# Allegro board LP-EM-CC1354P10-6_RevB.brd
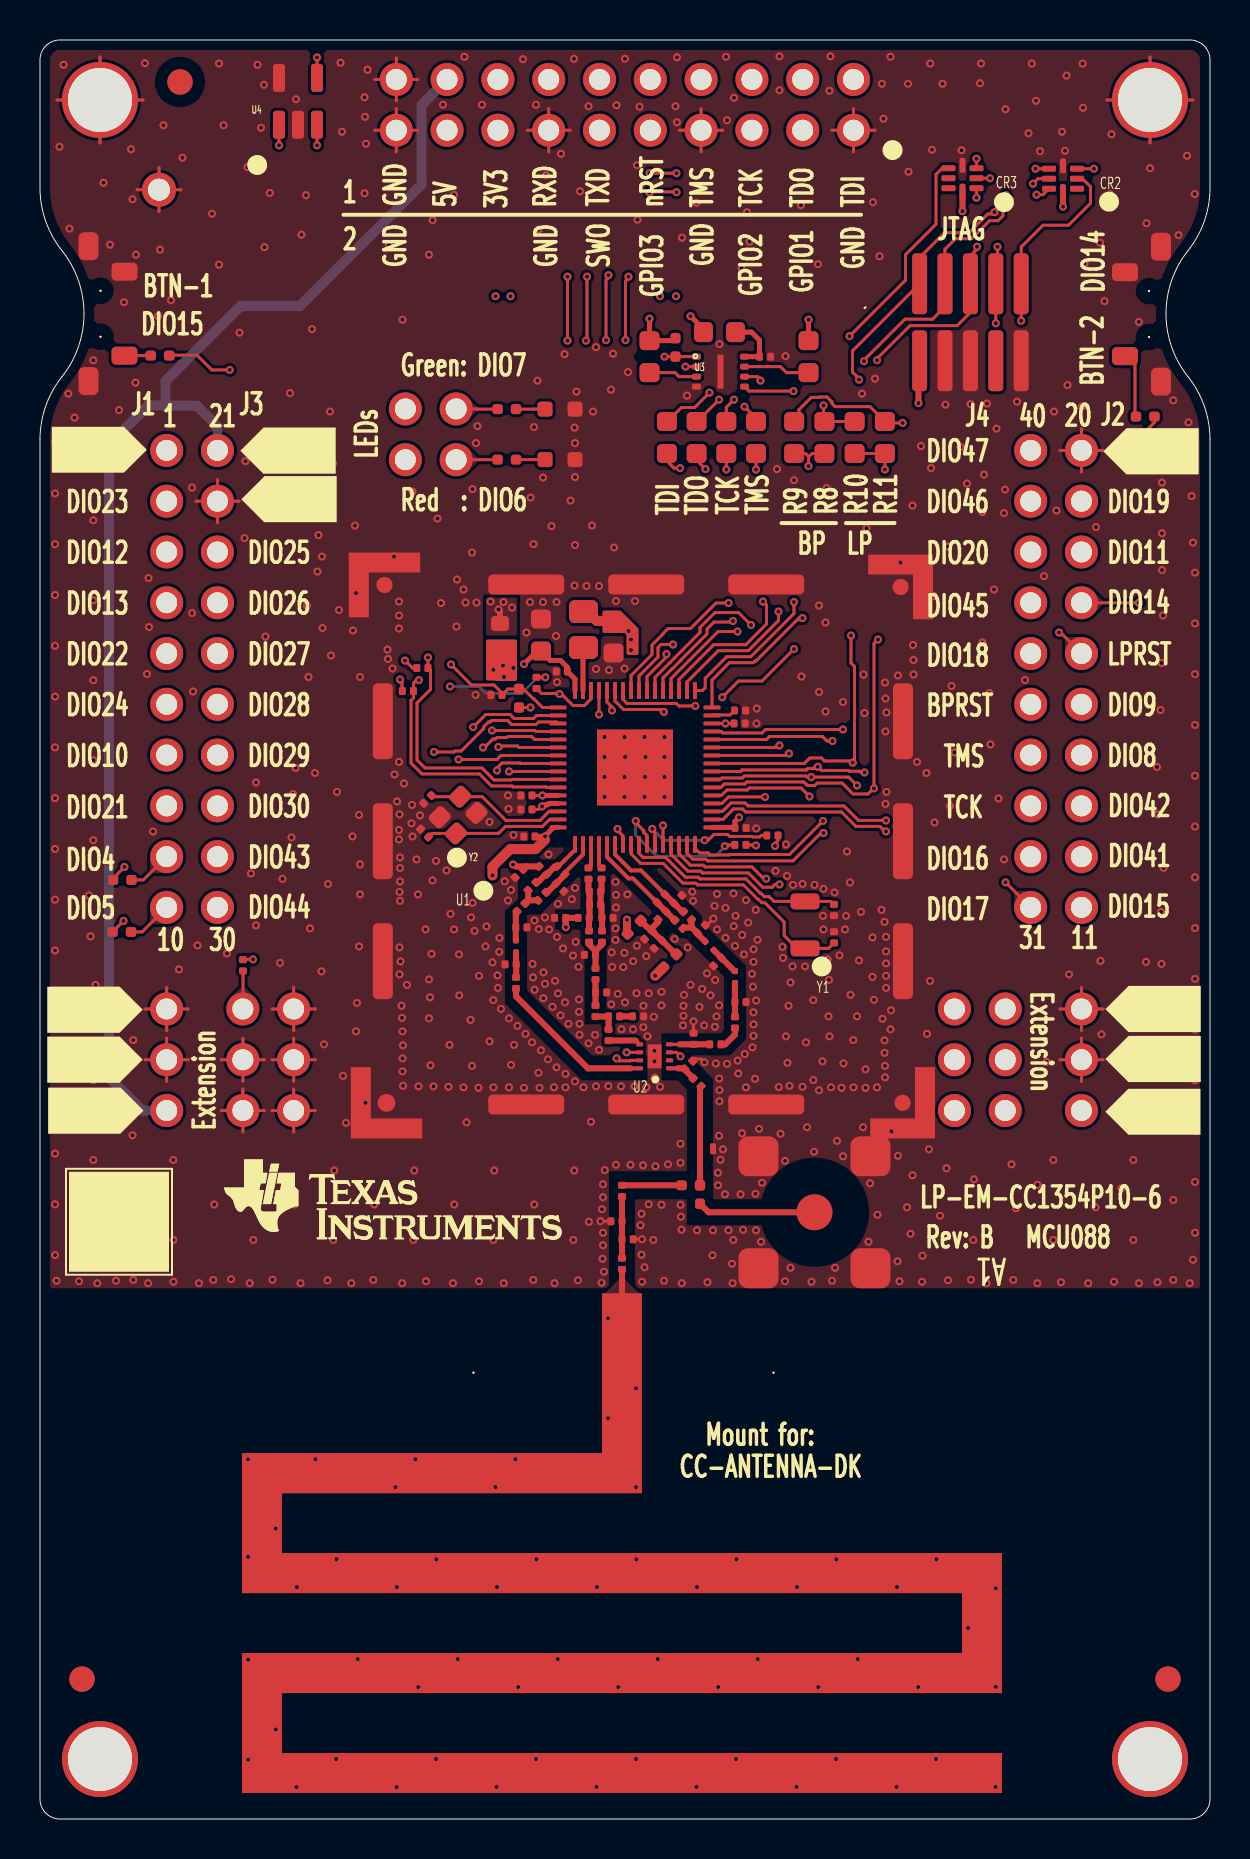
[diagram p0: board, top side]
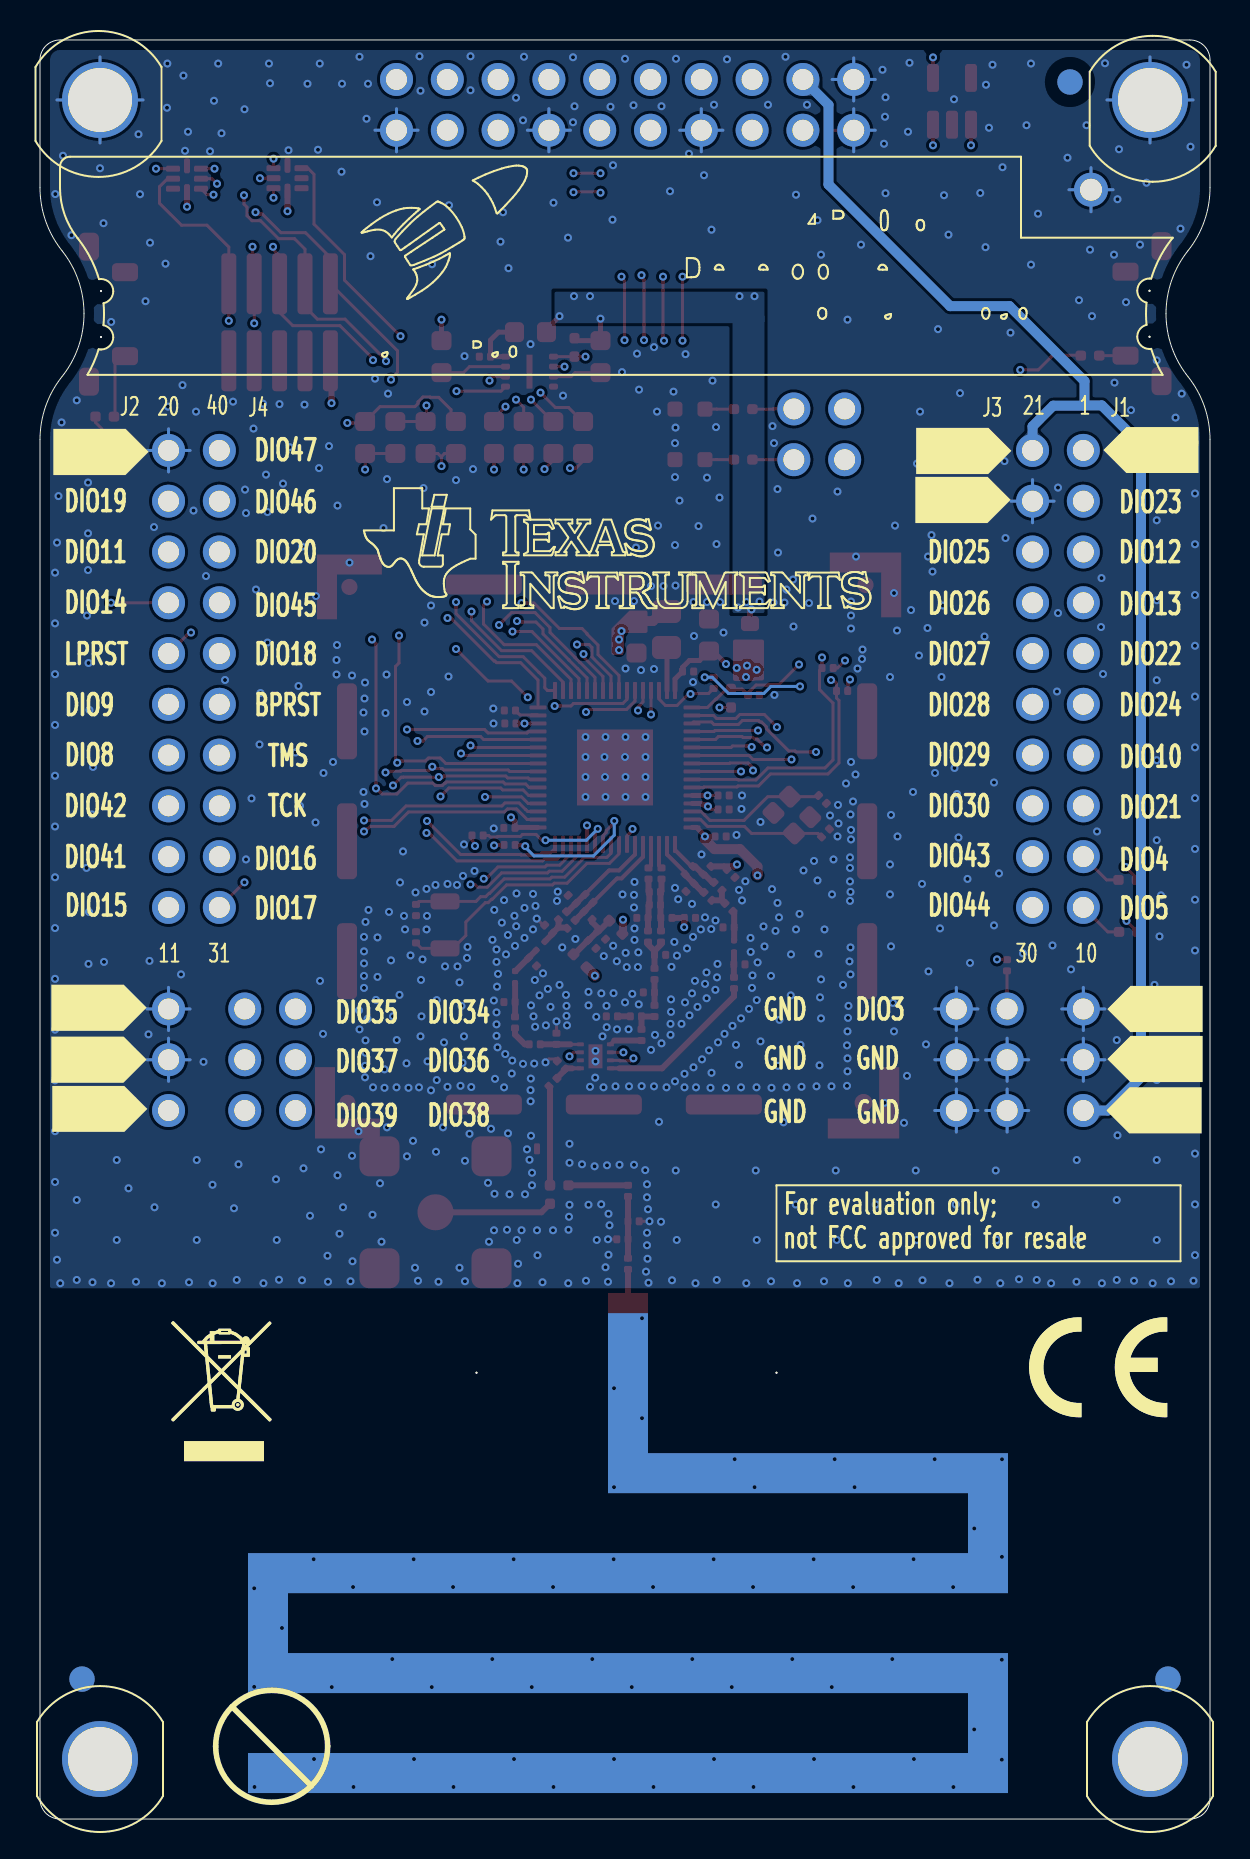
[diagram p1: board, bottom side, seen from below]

Outline 58.5 x 88.99 mm; copper layers: TOP, L2, L3, BOTTOM. Coordinates in mm from the lower left corner of the outline.
Outline path: 0,87.99 0,81.6 arc(0.28,79.93) 1.1,78.45 arc(1.92,76.97) 2.2,75.3 arc(1.92,73.63) 1.1,72.15 arc(0.28,70.67) 0,69 0,1 arc(0.29,0.29) 1,0 57.5,0 arc(58.21,0.29) 58.5,1 58.5,69 arc(58.22,70.67) 57.4,72.15 arc(56.58,73.63) 56.3,75.3 arc(56.58,76.97) 57.4,78.45 arc(58.22,79.93) 58.5,81.6 58.5,87.99 arc(58.21,88.7) 57.5,88.99 1,88.99 arc(0.29,88.7) 0,87.99

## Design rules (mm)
constraint set DEFAULT: min track width 0.15
nets with their own width: min track width 0.15; nets GND VDDR VDDS WMCU_VDD

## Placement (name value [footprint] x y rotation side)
A1  868MHz/2440MHz  [ANTENNA_DN024N]  29.1 25.8 180 top
C1  22uF  [CAPC1608X100A2N]  28.67 59.93 270 top
C2  22uF  [CAPC1608X100A2N]  25.05 58.43 90 top
C3  0.1uF  [CAPC0603X35B2N]  26.38 57.4 180 top
C4  0.1uF  [CAPC0603X35B2N]  34.75 49.57 0 top
C5  0.1uF  [CAPC0603X35B2N]  34.7 54.8 0 top
C6  0.1uF  [CAPC0603X35B2N]  24.6 51.2 180 top
C7  0.1uF  [CAPC0603X35B2N]  24.6 50.5 180 top
C8  0.1uF  [CAPC0603X35B2N]  24.75 49.15 180 top
C9  1uF  [CAPC0603X40B2N]  34.72 55.45 0 top
C11  12pF  [CAPC0603X35B2N]  23.75 47.1 45 top
C12  1pF  [CAPC0603X35B2N]  26.2 46.4 135 top
C13  1pF  [CAPC0603X35B2N]  24.8 46.85 225 top
C14  0.9pF  [CAPC0603X35B2N]  24.35 44.6 180 top
C15  0.6pF  [CAPC0603X35B2N]  23.25 42.75 0 top
C16  12pF  [CAPC0603X35B2N]  23.8 42.1 270 top
C17  47pF  [CAPC1005X60B2N]  33 30.78 90 top
C18  47pF  [CAPC1005X60B2N]  33 31.7 180 top
C27  100pF  [CAPC0603X35B2N]  28.42 39.5 270 top
C31  1.5pF  [CAPC0603X35B2N]  32.09 46.2 225 top
C32  1.5pF  [CAPC0603X35B2N]  31.75 44.95 315 top
C33  12pF  [CAPC0603X35B2N]  30.62 44.41 225 top
C34  10nF  [CAPC0603X35B2N]  31.1 43.94 225 top
C35  1pF  [CAPC0603X35B2N]  32.87 44.32 45 top
C37  1.5pF  [CAPC0603X35B2N]  33.67 42.68 45 top
C38  1.5pF  [CAPC0603X35B2N]  35.3 40.87 180 top
C39  12pF  [CAPC0603X35B2N]  34.75 40.12 270 top
C50  12pF  [CAPC0603X35B2N]  39.7 43.82 90 top
C51  15pF  [CAPC0603X35B2N]  39.7 45.75 270 top
C52  7.5pF  [CAPC0603X35B2N]  19.42 49.12 135 top
C53  7.5pF  [CAPC0603X35B2N]  19.57 51.2 225 top
C54  0.1uF  [CAPC0603X35B2N]  23.1 56.22 180 top
C55  0.1uF  [CAPC0603X35B2N]  35.97 73.15 0 top
C56  100pF  [CAPC0603X35B2N]  25.72 45.07 0 top
C57  3pF  [CAPC0603X35B2N]  27.45 44.43 270 top
C58  2.6pF  [CAPC0603X35B2N]  27.47 46.38 0 top
C59  3pF  [CAPC0603X35B2N]  27.77 43.22 180 top
C60  7pF  [CAPC0603X35B2N]  27.77 41.35 0 top
C61  3pF  [CAPC0603X35B2N]  28.1 45.07 0 top
C62  1.5pF  [CAPC0603X35B2N]  32.68 38.75 90 top
C63  4.7pF  [CAPC0603X35B2N]  32.24 37.52 45 top
CR1  TPD1E0B04DPY  [SON65P100X60X45-2A2N]  33.65 33.53 180 top
CR2  TPD6E004RSE  [QFNFC50P150X150X60-8A2N]  51.85 81.55 90 top
CR3  TPD6E004RSE  [QFNFC50P150X150X60-8A2N]  46.82 81.57 90 top
CR4  LPL296-J2L2-25  [LEDC1707X65N]  26.75 70.53 180 top
CR5  LS L296-P2Q2-1  [LEDC1708X67N]  26.75 68 180 top
FIDU1  FIDU_1.27mm  [FID127X142]  7 86.89 0 top
FIDU2  FIDU_1.27mm  [FID127X142]  2.1 7 0 top
FIDU3  FIDU_1.27mm  [FID127X142]  56.4 7 0 top
FIDU4  FIDU_1.27mm  [FID127X142]  7 86.89 180 bottom
FIDU5  FIDU_1.27mm  [FID127X142]  2.1 7 180 bottom
FIDU6  FIDU_1.27mm  [FID127X142]  56.4 7 180 bottom
FL1  BLM18HE152SN1  [FIL_BLM18HE152SN1DN]  23 58.4 90 top
J1  SSQ-110-23-L-D  [SAMTEC_SSQ11023LD_A2B]  6.33 68.46 0 bottom
J2  SSQ-110-23-L-D  [SAMTEC_SSQ11023LD_A2B]  49.53 68.46 0 bottom
J3  SMA-10V21-TGG  [HUSTSAN_SMA10V21TGGAN]  38.72 30.35 0 top
J4  SFH11-PBPC-D10-RA-BK  [SULLINS_SFH11PBPCD10RABK_A2B]  40.67 84.48 90 top
L1  6.8uH  [INDC2012X150A2N]  27.17 60.4 270 top
L11  20nH  [INDC0603X33A2N]  25.85 47.65 315 top
L12  3.7nH  [INDC0603X33A2N]  24.95 47.65 315 top
L13  3.7nH  [INDC0603X33A2N]  25.3 46.35 225 top
L14  3.4nH  [INDC0603X33A2N]  24.25 45.8 225 top
L15  3.9nH  [IND_LQP03HQ_A2N]  23.8 43.95 270 top
L27  6.8nH  [INDC0603X33A2N]  27.77 40.7 270 top
L34  6.8nH  [INDC0603X33A2N]  30.85 45.85 45 top
L35  2.4nH  [INDC0603X33A2N]  30.9 45 45 top
L36  2.4nH  [INDC0603X33A2N]  32.18 45.38 315 top
L37  3nH  [IND_LQP03HQ_A2N]  33.26 43.89 315 top
L39  3nH  [IND_LQP03HQ_A2N]  34.75 42.41 270 top
L40  10nH  [INDC0603X33A2N]  26.9 45.07 0 top
L41  3.4nH  [INDC0603X33A2N]  27.42 47.57 270 top
L42  22nH  [INDC0603X33A2N]  27.47 45.72 0 top
L43  6.8nH  [INDC0603X33A2N]  27.77 42.55 270 top
L44  3.4nH  [INDC0603X33A2N]  28.07 47.57 270 top
L45  10nH  [INDC0603X33A2N]  28.1 44.43 270 top
LBL1  TI_LOGO  [TI_LOGO_1]  10.2 33 0 top
LBL2  TRASH_7mm  [TRASH_7MM]  51.3 17.9 180 bottom
LBL3  ESD_LABEL_5x5mm  [ESD_LABEL_5X5]  1.45 27.38 0 top
LBL4  CE_label  [CE_MARKING]  6.42 20.1 180 bottom
LBL5  -  [LABEL_FOR_EVALUATION_ONLY]  21.52 28.05 180 bottom
M1  SNT-100-BK-G  [SAMTEC_SNT100BKG]  22.07 69.25 180 top
M2  SNT-100-BK-G  [SAMTEC_SNT100BKG]  22.07 71.8 180 top
M3  DCB-12D  [MECH_DCB12D_A2B]  2.86 85.55 180 bottom
M4  DCB-12D  [MECH_DCB12D_A2B]  55.57 85.79 180 bottom
M5  DCB-12D  [MECH_DCB12D_A2B]  3 3 180 bottom
M6  DCB-12D  [MECH_DCB12D_A2B]  55.5 3 180 bottom
MH1  HOLE_3.2mm_PAD_3.8mm_PTH  [MTG320_380]  3 3 0 top
MH2  HOLE_3.2mm_PAD_3.8mm_PTH  [MTG320_380]  55.5 3 0 top
MH3  HOLE_3.2mm_PAD_3.8mm_PTH  [MTG320_380]  3 85.99 0 top
MH4  HOLE_3.2mm_PAD_3.8mm_PTH  [MTG320_380]  55.5 85.99 0 top
MH5  HOLE_1.1mm_PTH  [MTG110_170]  5.95 81.5 0 top
NOREF  -  []  -1.77 89.3 0 top
NOREF#2  -  []  51.45 66 0 top
NOREF#3  -  []  -4.35 67.3 0 top
NOREF#4  -  []  53.05 34 0 top
NOREF#5  -  []  0.41 88.8 0 top
NOREF#6  -  []  -2.05 32.9 0 top
NOREF#7  -  []  51.55 35.6 0 top
NOREF#8  -  []  51.55 38.1 0 top
NOREF#9  -  []  0 -28.78 0 top
NOREF#10  -  []  8.35 65.9 0 top
NOREF#11  -  []  -1.95 38.1 0 top
NOREF#12  -  []  8.35 63.6 0 top
NOREF#13  -  []  0.23 75.46 0 top
NOREF#14  -  []  53.23 0 90 top
NOREF#15  -  []  0 86.37 0 top
NOREF#16  -  []  -45.65 -52.85 0 top
NOREF#17  #VALUE  [unnamed#2]  21.67 22.32 0 top
NOREF#18  -  []  -1.95 35.6 0 top
NOREF#19  -  []  5.55 67.1 180 bottom
NOREF#20  -  []  17.15 65.9 180 bottom
NOREF#21  -  []  6.85 38.1 180 bottom
NOREF#22  -  []  17.05 63.6 180 bottom
NOREF#23  -  []  51.48 89.52 180 bottom
NOREF#24  -  []  60.25 38.2 180 bottom
NOREF#25  -  []  60.15 66 180 bottom
NOREF#26  -  []  6.85 32.9 180 bottom
NOREF#27  -  []  57.95 34.3 180 bottom
NOREF#28  -  []  6.85 35.6 180 bottom
NOREF#29  -  []  60.25 35.6 180 bottom
P1  BB02-HJ041-KB1-603000  [GRADCONN_BB02HJ041KB1603000_A2B]  20.81 68 90 top
P2  BB02-HC031-KB1-603000  [GRADCONN_BB02HC031KB1603000_A2B]  6.33 35.44 90 top
P3  BB02-HC031-KB1-603000  [GRADCONN_BB02HC031KB1603000_A2B]  52.07 35.44 90 top
P4  BB02-HJ061-KB1-603000  [GRADCONN_BB02HJ061KB1603000_A2B]  10.14 40.52 270 top
P5  BB02-HJ061-KB1-603000  [GRADCONN_BB02HJ061KB1603000_A2B]  45.72 40.52 270 top
P6  FTSH-105-01-F-DV-K  [SAMTEC_FTSH10501FDVK_A2N]  43.98 72.94 0 top
R1  100k  [RESC1005X40B2N]  23.95 56.53 270 top
R2  3.3k  [RESC1005X40B2N]  4.55 44.38 180 top
R3  3.3k  [RESC1005X40B2N]  4.57 46.97 180 top
R4  0  [RESC1608X55A2N]  35.8 68.31 90 top
R5  0  [RESC1608X55A2N]  34.32 68.31 90 top
R6  0  [RESC1608X55A2N]  32.83 68.31 90 top
R7  0  [RESC1608X55A2N]  31.35 68.31 90 top
R8  0  [RESC1608X55A2N]  39.22 68.31 90 top
R9  0  [RESC1608X55A2N]  37.71 68.31 90 top
R10  0  [RESC1608X55A2N]  40.73 68.31 90 top
R11  0  [RESC1608X55A2N]  42.25 68.31 90 top
R12  100  [RESC1005X40B2N]  5.54 73.2 0 top
R13  100  [RESC1005X40B2N]  54.8 70.15 0 top
R14  220  [RESC1005X40B2N]  23.8 70.52 180 top
R15  180  [RESC1005X40B2N]  23.8 68 180 top
R16  0  [RESC0603X35B2N]  10.15 42.43 90 top
R17  0  [RESC0603X35B2N]  35.3 48.72 180 top
R18  0  [RESC0603X35B2N]  36.9 49.2 180 top
R19  0  [RESC0603X35B2N]  24.82 56.55 90 top
R20  0  [RESC0603X35B2N]  19.4 57.57 180 top
R21  0  [RESC0603X35B2N]  18.67 56.43 180 top
R22  0  [RESC1608X55A2N]  38.42 72.35 90 top
R23  0  [RESC1608X55A2N]  30.47 72.35 90 top
R24  2.2k  [RESC1005X40B2N]  31.77 73.15 90 top
R25  0  [RESC1608X55A2N]  34.77 74.38 180 top
R41  0  [RESC1005X40B2N]  30.03 44.94 225 top
R42  0  [RESC1005X40B2N]  31.83 43.25 225 top
SC1  BMIS-203-C  [MECH_BMIS203C]  16.82 35.43 0 top
SF1  BMI-S-203-F  [MECH_BMIS203_A2N]  17.42 35.72 0 top
SW1  1188E-1K2  [SW_1188E1K2V_A2N]  2.42 78.68 270 top
SW2  1188E-1K2  [SW_1188E1K2V_A2N]  56.05 71.9 90 top
U1  CC1354P106T0RSK  [QFNFC40P800X800X100-65A2N]  26.75 48.75 0 top
U2  SKY13317-373  [SON40P150X150X50-9A2N]  31.48 37.55 90 top
U3  MX25R8035FZUIL0  [SON50P300X200X60-9B2L]  32.82 73.15 270 top
U4  CAT24C08TDI  [SOT95P280X100-5A2N]  11.95 84.75 0 top
Y1  32.768kHz  [XTAL_TZ3581F_A2N]  38.25 43.55 90 top
Y2  48MHz  [OSCCC200X160X50-4A2N]  20.8 49.3 45 top
Z1  2.5pF  [CAPC0603X35B2N]  29.1 31.7 270 top
Z2  47pF  [CAPC0603X35B2N]  29.1 28.05 270 top
Z3  5.6pF  [CAPC0603X35B2N]  28.54 29.9 0 top
Z4  27nH  [INDC0603X33A2N]  29.1 29 0 top
Z7  3.9pF  [CAPC0603X35B2N]  28.42 40.15 0 top
Z8  0.6nH  [INDC0603X33A2N]  29.62 40.15 0 top
Z44  0  [RESC0603X35B2N]  33.48 38.75 0 top
Z45  0  [RESC0603X35B2N]  33.05 36.65 135 top

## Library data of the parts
A1 = ANTENNA_PCB: User Part Number: #PN
C1 C2 = CAPACITOR: User Part Number: #PN; alternate symbols: (CAPC1608X100A2L,CAPC1608X100A2M)
C3-C8 C11-C16 C27 C31-C35 C37-C39 C50-C63 Z1-Z3 Z7 = CAPACITOR: User Part Number: #PN; alternate symbols: (CAPC0603X35B2L,CAPC0603X35B2M)
C9 = CAPACITOR: User Part Number: #PN; alternate symbols: (CAPC0603X40B2L,CAPC0603X40B2M)
C17 C18 = CAPACITOR: User Part Number: #PN
CR1 = DIODE_TVS_BIDIR_S: User Part Number: #PN
CR2 CR3 = DIODE_TVS_TPD6E004_QFN8_V1: User Part Number: #PN; alternate symbols: (QFNFC50P150X150X60-8A2L,QFNFC50P150X150X60-8A2M)
CR4 = LED: alternate symbols: (LEDC1707X65L,LEDC1707X65M)
CR5 = LED: alternate symbols: (LEDC1708X67L,LEDC1708X67M)
FIDU1-FIDU6 = FIDMARK
FL1 = FILTER_2PIN: alternate symbols: (FIL_BLM18HE152SN1DL,FIL_BLM18HE152SN1DM)
J1 J2 = CONN_HEADER_2X10_J_S_V1: User Part Number: #PN; alternate symbols: (SAMTEC_SSQ11023LD_A2C,SAMTEC_SSQ11023LD_A2A)
J3 = CONN_COAX_1_4: alternate symbols: (HUSTSAN_SMA10V21TGGL,HUSTSAN_SMA10V21TGGM)
J4 = CONN_HEADER_2X10_P_V3: User Part Number: #PN; alternate symbols: (SULLINS_SFH11PBPCD10RABK_A2A,SULLINS_SFH11PBPCD10RABK_A2C)
L1 = INDUCTOR: User Part Number: #PN; alternate symbols: (INDC2012X150A2L,INDC2012X150A2M)
L11-L14 L27 L34-L36 L40-L45 Z4 Z8 = INDUCTOR: User Part Number: #PN; alternate symbols: (INDC0603X33A2L,INDC0603X33A2M)
L15 L37 L39 = INDUCTOR: User Part Number: #PN; alternate symbols: (IND_LQP03HQ_A2L,IND_LQP03HQ_A2M)
LBL1 = TI_LOGO_V1
LBL2 = TRASH_V2: User Part Number: #PN
LBL3 = ESD_LABEL: User Part Number: #PN
LBL4 = CE_LABEL_V1
LBL5 = LABEL_FOR_EVALUATOIN_ONLY: User Part Number: #PN
M1 M2 = MECH_SHUNT_JUMPER_V1: User Part Number: #PN
M3-M6 = MECH_SPACERS_SUPPORT_V1: User Part Number: #PN
MH1-MH5 = HOLE_PTH
NOREF#17 = -: User Part Number: #PN
P1 = CONN_HEADER_2X2_P: User Part Number: #PN; alternate symbols: (GRADCONN_BB02HJ041KB1603000_A2C,GRADCONN_BB02HJ041KB1603000_A2A)
P2 P3 = CONN_HEADER_3_P_S: User Part Number: #PN; alternate symbols: (GRADCONN_BB02HC031KB1603000_A2C,GRADCONN_BB02HC031KB1603000_A2A)
P4 P5 = CONN_HEADER_2X3_P_V2: User Part Number: #PN; alternate symbols: (GRADCONN_BB02HJ061KB1603000_A2A,GRADCONN_BB02HJ061KB1603000_A2C)
P6 = CONN_HEADER_2X5: User Part Number: #PN; alternate symbols: (SAMTEC_FTSH10501FDVK_A2L,SAMTEC_FTSH10501FDVK_A2M)
R1-R3 R12-R15 R24 R41 R42 = RESISTOR: User Part Number: #PN
R4-R11 R22 R23 R25 = RESISTOR: User Part Number: #PN; alternate symbols: (RESC1608X55A2L,RESC1608X55A2M)
R16-R21 Z44 Z45 = RESISTOR: User Part Number: #PN; alternate symbols: (RESC0603X35B2L,RESC0603X35B2M)
SC1 = SHIELD_COVER: User Part Number: #PN
SF1 = SHIELD_COVER_BMIS-203
SW1 SW2 = SWITCH_TACT_V2: alternate symbols: (SW_1188E1K2V_A2L,SW_1188E1K2V_A2M)
U1 = IC_RF_CC1354P106T0RSK_VQFN64: User Part Number: #PN; alternate symbols: (QFNFC40P800X800X100-65A2L,QFNFC40P800X800X100-65A2M)
U2 = IC_RF_SKY13317-373LF_MLP8: User Part Number: #PN
U3 = IC_FLASH_MX25R8035F_USON8: User Part Number: #PN; alternate symbols: (SON50P300X200X60-9B2L,SON50P300X200X60-9B2M)
U4 = IC_EEPROM_CAT24C08_TSOT23-5: User Part Number: #PN; alternate symbols: (SOT95P280X100-5A2L,SOT95P280X100-5A2M)
Y1 = XTAL: User Part Number: #PN; alternate symbols: (XTAL_TZ3581F_A2L,XTAL_TZ3581F_A2M)
Y2 = XTAL_4PINS_1_3: User Part Number: #PN; alternate symbols: (OSCCC200X160X50-4A2L,OSCCC200X160X50-4A2M)

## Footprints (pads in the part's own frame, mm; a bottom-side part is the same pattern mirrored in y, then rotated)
ANTENNA_DN024N
  rect 2x1 smd: 1(0,0)
CAPC0603X35B2N
  custom 0.087x0.087 smd: 1(0,0) 2(0.56,0)
CAPC0603X40B2N
  custom 0.087x0.087 smd: 1(0,0) 2(0.56,0)
CAPC1005X60B2N
  custom 0.125x0.125 smd: 1(0,0) 2(0.924,0)
CAPC1608X100A2N
  custom 0.237x0.237 smd: 1(0,0) 2(1.6,0)
FID127X142
  round 1.27 smd: 1(0,0)
FIL_BLM18HE152SN1DN
  custom 0.188x0.188 smd: 1(0,0) 2(1.4,0)
GRADCONN_BB02HC031KB1603000_A2B
  round 1.65 hole 1.05: 1(0,0) 2(2.54,0) 3(5.08,0)
GRADCONN_BB02HJ041KB1603000_A2B
  round 1.65 hole 1.05: 1(0,0) 2(0,2.54) 3(2.54,0) 4(2.54,2.54)
GRADCONN_BB02HJ061KB1603000_A2B
  round 1.65 hole 1.05: 1(0,0) 2(0,2.54) 3(2.54,0) 4(2.54,2.54) 5(5.08,0) 6(5.08,2.54)
HUSTSAN_SMA10V21TGGAN
  round 1.8 smd: 1(0,0)
  custom 0.5x0.5 smd: 2(-2.8,-2.8) 3(2.8,-2.8) 4(2.8,2.8) 5(-2.8,2.8)
IND_LQP03HQ_A2N
  custom 0.075x0.075 smd: 1(0,0) 2(0.6,0)
INDC0603X33A2N
  custom 0.087x0.087 smd: 1(0,0) 2(0.56,0)
INDC2012X150A2N
  custom 0.287x0.287 smd: 1(0,0) 2(1.8,0)
LEDC1707X65N
  custom 0.188x0.188 smd: 1(0,0) 2(1.501,0)
LEDC1708X67N
  custom 0.188x0.188 smd: 1(0,0) 2(1.501,0)
MECH_BMIS203_A2N
  custom 0.892x0.892 smd: 1(-0.1,0.1)
  custom 0.25x0.25 smd: 2(6.885,0.015) 3(12.885,0.015) 4(18.885,0.015) 6(25.725,7.185) 7(25.725,13.185) 8(25.725,19.185) 10(18.885,26.025) 11(12.885,26.025) 12(6.885,26.025) 14(-0.285,19.185) 15(-0.285,13.185) 16(-0.285,7.185)
  custom 0.81x0.81 smd: 5(25.705,0.1) 9(25.605,25.905) 13(-0.2,26.005)
MTG110_170
  round 1.699 hole 1.1: 1(0,0)
MTG320_380
  round 3.8 hole 3.2: 1(0,0)
OSCCC200X160X50-4A2N
  custom 0.212x0.212 smd: 1(0,0) 2(1.45,0) 3(1.45,1.15) 4(0,1.15)
QFNFC40P800X800X100-65A2N
  custom 0.05x0.05 smd: 1(0,0) 2(0.4,0) 3(0.8,0) 4(1.2,0) 5(1.6,0) 6(2,0) 7(2.4,0) 8(2.8,0) 9(3.2,0) 10(3.6,0) 11(4,0) 12(4.4,0) 13(4.8,0) 14(5.2,0) 15(5.6,0) 16(6,0) 17(6.85,0.85) 18(6.85,1.25) 19(6.85,1.65) 20(6.85,2.05) 21(6.85,2.45) 22(6.85,2.85) 23(6.85,3.25) 24(6.85,3.65) 25(6.85,4.05) 26(6.85,4.45) 27(6.85,4.85) 28(6.85,5.25) 29(6.85,5.65) 30(6.85,6.05) 31(6.85,6.45) 32(6.85,6.85) 33(6,7.7) 34(5.6,7.7) 35(5.2,7.7) 36(4.8,7.7) 37(4.4,7.7) 38(4,7.7) 39(3.6,7.7) 40(3.2,7.7) 41(2.8,7.7) 42(2.4,7.7) 43(2,7.7) 44(1.6,7.7) 45(1.2,7.7) 46(0.8,7.7) 47(0.4,7.7) 48(0,7.7) 49(-0.85,6.85) 50(-0.85,6.45) 51(-0.85,6.05) 52(-0.85,5.65) 53(-0.85,5.25) 54(-0.85,4.85) 55(-0.85,4.45) 56(-0.85,4.05) 57(-0.85,3.65) 58(-0.85,3.25) 59(-0.85,2.85) 60(-0.85,2.45) 61(-0.85,2.05) 62(-0.85,1.65) 63(-0.85,1.25) 64(-0.85,0.85)
  rect 3.8x3.8 smd: 65(3,3.85)
QFNFC50P150X150X60-8A2N
  custom 0.075x0.075 smd: 1(0,0) 2(0.5,0) 3(1,0) 4(1.145,0.7) 5(1,1.4) 6(0.5,1.4) 7(0,1.4) 8(-0.145,0.7)
RESC0603X35B2N
  custom 0.087x0.087 smd: 1(0,0) 2(0.56,0)
RESC1005X40B2N
  custom 0.125x0.125 smd: 1(0,0) 2(0.924,0)
RESC1608X55A2N
  custom 0.237x0.237 smd: 1(0,0) 2(1.6,0)
SAMTEC_FTSH10501FDVK_A2N
  custom 0.188x0.188 smd: 1(0,0) 2(0,3.85) 3(1.27,0) 4(1.27,3.85) 5(2.54,0) 6(2.54,3.85) 7(3.81,0) 8(3.81,3.85) 9(5.08,0) 10(5.08,3.85)
SAMTEC_SSQ11023LD_A2B
  round 1.65 hole 1.05: 1(0,0) 2(2.54,0) 3(0,2.54) 4(2.54,2.54) 5(0,5.08) 6(2.54,5.08) 7(0,7.62) 8(2.54,7.62) 9(0,10.16) 10(2.54,10.16) 11(0,12.7) 12(2.54,12.7) 13(0,15.24) 14(2.54,15.24) 15(0,17.78) 16(2.54,17.78) 17(0,20.32) 18(2.54,20.32) 19(0,22.86) 20(2.54,22.86)
SON40P150X150X50-9A2N
  custom 0.05x0.05 smd: 1(0,0) 2(0.4,0) 3(0.8,0) 4(1.2,0) 5(1.2,1.5) 6(0.8,1.5) 7(0.4,1.5) 8(0,1.5)
  rect 1.2x0.7 smd: 9(0.6,0.75)
SON50P300X200X60-9B2L
  custom 0.075x0.075 smd: 1(0,0) 2(0.5,0) 3(1,0) 4(1.5,0) 5(1.5,2.4) 6(1,2.4) 7(0.5,2.4) 8(0,2.4)
  rect 1.7x0.3 smd: 9(0.75,1.2)
SON65P100X60X45-2A2N
  custom 0.075x0.075 smd: 1(0,0) 2(0.65,0)
SOT95P280X100-5A2N
  custom 0.15x0.15 smd: 1(0,0) 2(0.95,0) 3(1.9,0) 4(1.9,2.34) 5(0,2.34)
SULLINS_SFH11PBPCD10RABK_A2B
  round 1.65 hole 1.05: 1(0,0) 2(2.54,0) 3(0,2.54) 4(2.54,2.54) 5(0,5.08) 6(2.54,5.08) 7(0,7.62) 8(2.54,7.62) 9(0,10.16) 10(2.54,10.16) 11(0,12.7) 12(2.54,12.7) 13(0,15.24) 14(2.54,15.24) 15(0,17.78) 16(2.54,17.78) 17(0,20.32) 18(2.54,20.32) 19(0,22.86) 20(2.54,22.86)
SW_1188E1K2V_A2N
  round 0.099 hole 0.899 unplated: (2.229,0.6) (4.529,0.6)
  custom 0.25x0.25 smd: 1(0,0) 2(6.75,0)
  custom 0.225x0.225 smd: 3(1.275,1.8) 4(5.475,1.8)
unnamed#2
  round 0.099 hole 3.2 unplated: (0,0) (15,0)
XTAL_TZ3581F_A2N
  custom 0.2x0.2 smd: 1(0,0) 2(2.35,0)

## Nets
5V0_BP: J1.2 J4.18 P2.1 U4.4
GND: C1.2 C2.2 C3.2 C4.2 C5.2 C6.2 C7.2 C8.2 C9.2 C11.1 C12.1 C14.1 C15.1 C31.1 C33.2 C34.2 C35.2 C37.1 C38.1 C50.2 C51.2 C52.2 C53.2 C54.2 C55.2 C56.1 C59.2 C60.2 C61.2 C62.2 C63.2 CR1.1 CR2.4 CR3.4 CR4.1(C) CR5.1(C) J1.4 J2.2 J3.2 J3.3 J3.4 J3.5 J4.1 J4.7 J4.13 J4.19 J4.20 MH3.1 MH4.1 MH5.1 P2.2 P2.3 P3.2 P3.3 P4.2 P4.3 P4.4 P4.5 P4.6 P6.3 P6.5 P6.9 SF1.1 SF1.2 SF1.3 SF1.4 SF1.5 SF1.6 SF1.7 SF1.8 SF1.9(GND#9) SF1.10 SF1.11 SF1.12 SF1.13 SF1.14 SF1.15 SF1.16 SW1.1 SW1.2 SW1.3 SW2.1 SW2.2 SW2.4 U1.65 U2.9 U3.4 U3.9 U4.2 U4.5(WP) Y2.2 Y2.4(GND#4) Z3.1 Z4.2 Z8.2
VDDR: C1.1 C7.1 C8.1 L1.1 R42.2 U1.61 U1.64
VDDS: C2.1 C3.1 C4.1 C5.1 C6.1 FL1.1 R1.2 R41.2 U1.17 U1.30 U1.48 U1.60
BP_RESET: J2.11 R8.1 R9.1
DIO3: P4.1 R16.1 U1.12
DIO3_RF_PA: R16.2 U2.3
DIO4_SCL: J1.17 R3.1 U1.13
DIO5_SDA: J1.19 R2.1 U1.14
DIO6_RLED: P1.2 U1.15
DIO7_GLED: P1.4 U1.16
DIO8_MISO: J2.14 U1.18
DIO9_MOSI: J2.12 U1.19(DIO_9)
DIO10_SCLK: J1.13 U1.20
DIO11: J2.6 U1.21
DIO14_BTN2: J2.8 R13.2 U1.28
DIO15_BTN1: J2.20 R12.2 U1.29
DIO16_TDO: CR2.5 J4.4 P6.6 R6.2 U1.34
DIO17_TDI: CR2.3 J4.2 P6.8 R7.2 U1.35
DIO19: J2.4 U1.37
DIO20: J2.5 U1.38
DIO21: J1.15 U1.39
DIO22: J1.9 U1.40
DIO23_ANALOG: J1.3 U1.50
DIO24_ANALOG: J1.11 U1.51
DIO25_ANALOG: J1.6 U1.52
DIO26_ANALOG: J1.8 U1.53
DIO27_ANALOG: J1.10 U1.54
DIO28_ANALOG: J1.12 U1.55
DIO29_ANALOG: J1.14 U1.56
DIO30_ANALOG: J1.16 U1.57
DIO34: P5.1 R17.2 U1.10
DIO34_RF_2G4: R17.1 U2.7(V3)
DIO35: P5.2 R18.2 U1.11
DIO35_RF_SUB1G: R18.1 U2.6
DIO36_FLASH_MOSI: P5.3 U1.22 U3.5
DIO37_FLASH_MISO: P5.4 U1.23 U3.2
DIO38_FLASH_CS: P5.5 R24.1 U1.24 U3.1
DIO39_FLASH_SCLK: P5.6 U1.25 U3.6
DIO40: R8.2 R10.2 U1.41
DIO41: J2.18 U1.42
DIO42: J2.16 U1.43
DIO43: J1.18 U1.44
DIO44: J1.20 U1.45
DIO45: J2.7 R19.1 U1.46
DIO46: J2.3 R20.1 U1.58
DIO47: J2.1 R21.1 U1.59
LP_RESET: J2.10 R10.1 R11.1
RX_TX: C11.2 C56.2 L12.1 L40.1 U1.7
WMCU_RESET: C54.1 CR2.2 J4.10 P6.10 R1.1 R9.2 R11.2 U1.49
WMCU_RXD: J1.5 J4.14 U1.26
WMCU_SWO: CR3.5 J2.9 J4.11 U1.36
WMCU_TCK: CR2.6 J4.6 P6.4 R5.2 U1.33
WMCU_TMS: CR2.7 J4.8 P6.2 R4.2 U1.32
WMCU_TXD: J1.7 J4.12 U1.27
WMCU_VDD: CR2.8(VCC) CR3.8(VCC) FL1.2 J1.1 J4.16 P3.1 P6.1 R2.2 R3.2 R22.2 R23.2 R24.2 R25.2
XDS_BOARDID_SCL: J4.15 U4.1
XDS_BOARDID_SDA: J4.17 U4.3
XDS_GPIO1: CR3.1 J4.3 R19.2
XDS_GPIO2: CR3.2 J4.5 R20.2
XDS_GPIO3: CR3.3 J4.9 R21.2
N3099875: C13.1 L11.1 L12.2 U1.1
N3099951: C13.2 L13.2 L14.1
N3100073: C14.2 L14.2 L15.1
N3100081: C15.2 C16.1 L15.2
N3100105: C17.1 J3.1
N3100141: C12.2 L11.2 L13.1 U1.2
N3100321: C17.2 C18.1 CR1.2 Z45.1
N3100543: C16.2 U2.8
N3100575: C27.2 U2.5
N3100757: L41.1 U1.3
N3100925: L44.1 U1.4
N3100985: C32.1 L34.1 L35.2 U1.5
N3100993: C18.2 Z1.1
N3100997: C31.2 L34.2 L36.1 U1.6
N3101199: C50.1 U1.8 Y1.1
N3101207: C51.1 U1.9 Y1.2
N3101223: C52.1 U1.63 Y2.1
N3101377: Z1.2 Z2.1 Z3.2 Z4.1
N3101433: A1.1 Z2.2
N3101449: C53.1 U1.62 Y2.3
N3101953: C62.1 U2.4 Z44.1
N3109894: J2.13 R4.1
N3109960: J2.15 R5.1
N3110034: J2.17 R6.1
N3110086: J2.19 R7.1
N3110356: P1.1 R15.2
N3110380: P1.3 R14.2
N3110768: R12.1 SW1.4
N3110772: R13.1 SW2.3
N3110876: CR4.2 R14.1
N3110880: CR5.2 R15.1
N3111246: C55.1 R25.1 U3.8(VCC)
N3111262: R22.1 U3.7
N3111266: R23.1 U3.3
N3254079: L1.2 U1.47
N3281348: C9.1 U1.31
N3492676: C27.1 L27.2 Z7.1
N3492704: Z7.2 Z8.1
N3493209: C57.1 C58.1 L40.2 L41.2 L42.1
N3493257: C57.2 C59.1 L43.1 L45.2
N3493329: C60.1 L27.1 L43.2
N3493341: C58.2 C61.1 L42.2 L44.2 L45.1
N3546372: C33.1 C34.1 L35.1 R41.1 R42.1
N3546508: C32.2 C35.1 L36.2 L37.1
N3546612: C37.2 L37.2 L39.1
N3546624: C38.2 C39.1 L39.2
N3546636: C39.2 Z44.2
N3547384: C63.1 U2.1 Z45.2

Pads without a net: CR2 1; CR3 6 7; FIDU1 1; FIDU2 1; FIDU3 1; FIDU4 1; FIDU5 1; FIDU6 1; MH1 1; MH2 1; P6 7; U2 2

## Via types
v1: diameter 0.4, hole 0.2, TOP to BOTTOM, 1019 vias

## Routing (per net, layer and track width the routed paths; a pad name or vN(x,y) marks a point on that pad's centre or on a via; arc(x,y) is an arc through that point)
5V0_BP: length 75.4
  TOP w0.15: U4.4 v1(13.85,88.12)
  L3 w0.15: J4.18 20.35,87.3 19.26,88.39 14.02,88.39 13.85,88.23 v1(13.85,88.12)
  BOTTOM w0.5: J4.18 20.35,87.01 19.07,85.74 19.07,81.76 12.99,75.68 10.03,75.68 6.27,71.93 6.27,70.71 ; P2.1 5.11,35.44 3.45,37.1 3.45,68.75 5.41,70.71 6.27,70.71 ; J1.2 8.87,69.66 7.84,70.7 6.29,70.7 6.27,70.71
GND: length 307.2
  TOP w0.15: P4.3 10.14,39.06 ; P4.3 11.22,37.98 ; P4.3 10.14,36.9 ; P4.3 9.07,37.98 ; 25.44,83.4 J4.13 ; J4.13 26.51,84.48 ; J4.13 25.44,85.55 ; J4.13 24.36,84.48 ; 40.67,83.4 J4.1 ; J4.1 40.67,85.55 ; J4.1 39.6,84.48 ; J4.1 41.75,84.48 ; P2.3 6.33,41.6 ; P2.3 6.33,39.44 ; P2.3 7.41,40.52 ; P2.3 5.26,40.52 ; 5.26,37.98 P2.2 ; P2.2 6.33,36.9 ; P2.2 7.41,37.98 ; P2.2 6.33,39.06 ; MH4.1 57.65,85.99 ; MH4.1 55.5,83.84 ; MH4.1 55.5,88.14 ; MH4.1 53.35,85.99 ; 16.74,84.48 J4.19 ; J4.19 17.81,85.55 ; J4.19 17.81,83.4 ; J4.19 18.89,84.48 ; 52.07,36.9 P3.2 ; P3.2 52.07,39.06 ; P3.2 51,37.98 ; P3.2 53.15,37.98 ; 12.68,36.9 P4.4 ; P4.4 11.61,37.98 ; P4.4 12.68,39.06 ; P4.4 13.76,37.98 ; 17.81,85.94 J4.20 ; J4.20 17.81,88.09 ; J4.20 18.89,87.01 ; J4.20 16.74,87.01 ; 12.68,39.44 P4.2 ; P4.2 13.76,40.52 ; P4.2 12.68,41.6 ; P4.2 11.61,40.52 ; 32.67,39.31 v1(32.67,39.9) ; 4.85,81.5 MH5.1 ; MH5.1 5.95,80.4 ; MH5.1 5.95,82.6 ; MH5.1 7.05,81.5 ; 33.05,83.4 J4.7 ; J4.7 34.13,84.48 ; J4.7 31.98,84.48 ; J4.7 33.05,85.55 ; v1(33.66,45.04) 33.37,44.75 33.25,44.75 ; P4.5 10.14,36.52 ; P4.5 11.22,35.44 ; P4.5 9.07,35.44 ; P4.5 10.14,34.36 ; P3.3 53.15,40.52 ; P3.3 52.07,39.44 ; P3.3 51,40.52 ; P3.3 52.07,41.6 ; 3,83.84 MH3.1 ; MH3.1 0.85,85.99 ; MH3.1 3,88.14 ; MH3.1 5.15,85.99 ; J2.2 53.15,68.46 ; J2.2 52.07,69.54 ; J2.2 51,68.46 ; J2.2 52.07,67.38 ; Z4.2 v1(30.1,29) ; 11.61,35.44 P4.6 ; P4.6 12.68,36.52 ; P4.6 12.68,34.36 ; P4.6 13.76,35.44 ; C63.2 32.73,38.01 33.06,38.02 v1(33.22,37.85) ; v1(28.03,29.9) Z3.1 ; 7.8,65.92 J1.4 ; J1.4 8.87,67 ; J1.4 9.95,65.92 ; J1.4 8.87,64.84
  L2 w0.15: P2.2 7.41,37.98 ; P2.2 6.33,36.9 ; P2.2 5.26,37.98 ; P2.2 6.33,39.06 ; J4.20 18.89,87.01 ; J4.20 17.81,85.94 ; J4.20 16.74,87.01 ; J4.20 17.81,88.09 ; MH5.1 5.95,82.6 ; MH5.1 5.95,80.4 ; MH5.1 7.05,81.5 ; MH5.1 4.85,81.5 ; P3.2 53.15,37.98 ; P3.2 51,37.98 ; P3.2 52.07,39.06 ; P3.2 52.07,36.9 ; 33.05,83.4 J4.7 ; J4.7 33.05,85.55 ; J4.7 34.13,84.48 ; J4.7 31.98,84.48 ; 9.07,37.98 P4.3 ; P4.3 11.22,37.98 ; P4.3 10.14,36.9 ; P4.3 10.14,39.06 ; 12.68,36.9 P4.4 ; P4.4 11.61,37.98 ; P4.4 12.68,39.06 ; P4.4 13.76,37.98 ; P2.3 6.33,41.6 ; P2.3 7.41,40.52 ; P2.3 6.33,39.44 ; P2.3 5.26,40.52 ; MH4.1 57.65,85.99 ; MH4.1 55.5,83.84 ; MH4.1 55.5,88.14 ; MH4.1 53.35,85.99 ; MH3.1 5.15,85.99 ; MH3.1 3,83.84 ; MH3.1 0.85,85.99 ; MH3.1 3,88.14 ; 12.68,34.36 P4.6 ; P4.6 13.76,35.44 ; P4.6 12.68,36.52 ; P4.6 11.61,35.44 ; P3.3 53.15,40.52 ; P3.3 51,40.52 ; P3.3 52.07,41.6 ; P3.3 52.07,39.44 ; 10.14,34.36 P4.5 ; P4.5 9.07,35.44 ; P4.5 11.22,35.44 ; P4.5 10.14,36.52 ; J1.4 8.87,67 ; J1.4 8.87,64.84 ; J1.4 9.95,65.92 ; J1.4 7.8,65.92 ; J4.13 26.51,84.48 ; J4.13 24.36,84.48 ; J4.13 25.44,83.4 ; J4.13 25.44,85.55 ; 12.68,39.44 P4.2 ; P4.2 11.61,40.52 ; P4.2 12.68,41.6 ; P4.2 13.76,40.52 ; 17.81,83.4 J4.19 ; J4.19 16.74,84.48 ; J4.19 17.81,85.55 ; J4.19 18.89,84.48 ; 40.67,83.4 J4.1 ; J4.1 39.6,84.48 ; J4.1 40.67,85.55 ; J4.1 41.75,84.48 ; J2.2 53.15,68.46 ; J2.2 52.07,69.54 ; J2.2 52.07,67.38 ; J2.2 51,68.46
  L3 w0.15: 16.74,84.48 J4.19 ; J4.19 18.89,84.48 ; J4.19 17.81,85.55 ; MH4.1 57.65,85.99 ; MH4.1 55.5,83.84 ; MH4.1 55.5,88.14 ; MH4.1 53.35,85.99 ; 31.98,84.48 J4.7 ; J4.7 34.13,84.48 ; J4.7 33.05,85.55 ; J4.20 18.89,87.01 ; J4.20 17.81,85.94 ; J4.20 16.74,87.01 ; 3,83.84 MH3.1 ; MH3.1 5.15,85.99 ; MH3.1 3,88.14 ; MH3.1 0.85,85.99 ; 25.44,85.55 J4.13 25.93,85.59 ; 41.79,84.97 J4.1 41.75,84.48 ; 4.85,81.5 MH5.1 5.07,80.62
  BOTTOM w0.15: 5.26,40.52 P2.3 ; P2.3 6.33,41.6 ; P2.3 6.33,39.44 ; P2.3 7.41,40.52 ; 51,37.98 P3.2 ; P3.2 53.15,37.98 ; P3.2 52.07,39.06 ; P3.2 52.07,36.9 ; J4.20 18.89,87.01 ; J4.20 17.81,85.94 ; J4.20 17.81,88.09 ; J4.20 16.74,87.01 ; 0.85,85.99 MH3.1 ; MH3.1 3,88.14 ; MH3.1 3,83.84 ; MH3.1 5.15,85.99 ; 17.81,83.4 J4.19 ; J4.19 17.81,85.55 ; J4.19 16.74,84.48 ; 25.44,83.4 J4.13 ; J4.13 26.51,84.48 ; J4.13 24.36,84.48 ; J4.13 25.44,85.55 ; P4.3 10.14,39.06 ; P4.3 10.14,36.9 ; P4.3 9.07,37.98 ; P4.3 11.22,37.98 ; P2.2 7.41,37.98 ; P2.2 6.33,36.9 ; P2.2 6.33,39.06 ; P2.2 5.26,37.98 ; 52.07,39.44 P3.3 ; P3.3 53.15,40.52 ; P3.3 52.07,41.6 ; P3.3 51,40.52 ; MH4.1 55.5,88.14 ; MH4.1 57.65,85.99 ; MH4.1 55.5,83.84 ; MH4.1 53.35,85.99 ; 12.68,39.44 P4.2 ; P4.2 13.76,40.52 ; P4.2 11.61,40.52 ; P4.2 12.68,41.6 ; P4.4 13.76,37.98 ; P4.4 12.68,36.9 ; P4.4 11.61,37.98 ; P4.4 12.68,39.06 ; P4.6 12.68,36.52 ; P4.6 12.68,34.36 ; P4.6 13.76,35.44 ; P4.6 11.61,35.44 ; 52.07,67.38 J2.2 ; J2.2 52.07,69.54 ; J2.2 53.15,68.46 ; J2.2 51,68.46 ; J1.4 9.95,65.92 ; J1.4 7.8,65.92 ; J1.4 8.87,64.84 ; J1.4 8.87,67 ; 5.95,80.4 MH5.1 ; MH5.1 5.95,82.6 ; MH5.1 4.85,81.5 ; MH5.1 7.05,81.5 ; P4.5 11.22,35.44 ; P4.5 10.14,36.52 ; P4.5 9.07,35.44 ; P4.5 10.14,34.36 ; J4.7 33.05,85.55 ; J4.7 31.98,84.48 ; J4.7 33.05,83.4 ; J4.7 34.13,84.48 ; 40.67,83.4 J4.1 ; J4.1 41.75,84.48 ; J4.1 40.67,85.55 ; J4.1 39.6,84.48
  vias: v1(0.75,68.85) v1(0.75,66.31) v1(0.75,63.77) v1(0.75,61.23) v1(0.75,58.69) v1(0.75,56.15) v1(0.75,53.61) v1(0.75,51.07) v1(0.75,48.53) v1(0.75,45.99) v1(0.75,43.45) v1(0.75,40.91) v1(0.75,38.37) v1(0.75,35.83) v1(0.75,33.29) v1(0.75,30.75) v1(0.75,28.21) v1(0.82,26.93) v1(0.97,83.65) v1(1.17,87.75) v1(1.47,79.55) v1(1.41,71.3) v1(1.72,70.1) v1(1.95,26.9) v1(2.45,46.2) v1(2.52,44.15) v1(2.66,72.97) v1(2.66,68.97) v1(2.66,64.97) v1(2.66,60.97) v1(2.66,56.97) v1(2.66,52.97) v1(2.66,48.97) v1(2.66,36.97) v1(2.66,32.97) v1(2.66,28.97) v1(2.77,41.72) v1(2.87,26.8) v1(3.17,81.85) v1(3.5,78.75) v1(3.8,26.93) v1(3.95,70.47) v1(4.2,75.88) v1(4.55,83.52) v1(4.62,81.02) v1(4.66,38.97) v1(4.62,34.2) v1(4.66,30.97) v1(4.66,26.97) v1(4.8,78.25) v1(4.77,71.85) v1(5.25,87.82) v1(5.35,57.28) v1(5.42,62.07) v1(5.45,59.62) v1(5.41,26.8) v1(5.65,49.4) v1(5.9,75.18) v1(6,78.5) v1(6.17,84.73) v1(6.55,75.97) v1(6.66,32.97) v1(6.66,28.97) v1(6.67,26.88) v1(6.95,42.5) v1(7.12,83.1) v1(7.6,66.6) v1(7.6,60.32) v1(7.65,56.4) v1(7.88,43.7) v1(7.95,26.8) v1(8.6,80.3) v1(8.66,26.97) v1(8.71,30.74) v1(8.95,87.81) v1(8.95,77.75) v1(9.17,84.73) v1(9.35,43.3) v1(9.55,27) v1(9.97,74.35) v1(10.27,67.93) v1(10.22,64.07) v1(10.38,82.62) v1(10.49,26.8) v1(10.55,47.3) v1(10.66,28.97) v1(10.8,51.85) v1(10.8,44.7) v1(10.71,32.44) v1(10.88,87.75) v1(11.05,84.6) v1(11.2,86.75) v1(11.2,65.88) v1(11.22,78.62) v1(11.27,59.15) v1(11.49,81.34) v1(11.62,26.97) v1(12,42.82) v1(12.12,47.03) v1(12.5,71.32) v1(12.57,49.1) v1(12.65,51.28) v1(12.8,86.02) v1(12.77,52.57) v1(12.71,30.74) v1(12.95,69.07) v1(12.95,66.18) v1(13.07,79.25) v1(13.03,26.8) v1(13.3,81.23) v1(13.35,60.7) v1(13.42,57.12) v1(13.5,44.55) v1(13.6,74.53) v1(13.75,52.32) v1(13.88,62.4) v1(13.92,64.22) v1(14.07,42.4) v1(14.1,63.15) v1(14.12,59.57) v1(14.2,38.75) v1(14.38,65.75) v1(14.4,46.78) v1(14.38,26.95) v1(14.5,70.4) v1(14.55,58.2) v1(14.65,67.8) v1(14.66,28.97) v1(14.71,32.44) v1(14.85,51.38) v1(14.95,60.47) v1(15.02,87.85) v1(15.1,84.4) v1(15.15,37.18) v1(15.3,34.82) v1(15.57,26.8) v1(15.65,59.45) v1(15.62,49.15) v1(15.75,64.7) v1(15.8,61.32) v1(15.8,39.4) v1(15.85,40.82) v1(15.95,50.22) v1(15.95,43.65) v1(16,57.12) v1(16,47.75) v1(16,46.25) v1(16.22,86.12) v1(16.25,85.15) v1(16.3,83.8) v1(16.22,81.32) v1(16.27,35.82) v1(16.38,87.5) v1(16.66,26.97) v1(16.71,30.74) v1(17.38,58.5) v1(17.4,58.03) v1(17.45,78.75) v1(17.62,57.55) v1(17.7,63.15) v1(17.72,52.25) v1(17.85,50.9) v1(17.95,60.9) v1(17.95,60.2) v1(17.95,59.55) v1(17.95,52.88) v1(17.97,50.25) v1(17.95,49.47) v1(17.95,49) v1(17.97,46.38) v1(17.97,43.6) v1(17.97,42.25) v1(18,48.1) v1(18,47.57) v1(18,46.9) v1(18,45.93) v1(18.02,42.9) v1(18.07,40.68) v1(18.12,75) v1(18.2,51.8) v1(18.1,40.07) v1(18.12,39.4) v1(18.15,38.7) v1(18.12,38.05) v1(18.12,37.4) v1(18.15,36.68) v1(18.11,26.8) v1(18.35,41.72) v1(18.57,49.8) v1(18.62,66.4) v1(18.6,50.73) v1(18.62,49.15) v1(18.66,28.97) v1(18.71,32.44) v1(18.82,48) v1(18.9,46.25) v1(18.92,36.65) v1(19,50.2) v1(19.27,44.5) v1(19.3,26.9) v1(19.45,78.25) v1(19.45,42) v1(19.45,40.05) v1(19.57,43.28) v1(19.5,41.1) v1(19.52,37.7) v1(19.62,79.97) v1(19.62,46.95) v1(19.67,36.65) v1(19.8,47.93) v1(19.88,65.05) v1(20.05,60.82) v1(20.15,85.75) v1(20.32,47.45) v1(20.47,38.72) v1(20.42,36.62) v1(20.52,45.28) v1(20.65,26.8) v1(20.7,81.25) v1(20.7,44.5) v1(20.71,30.74) v1(20.85,62) v1(20.82,59.65) v1(20.95,43.25) v1(20.96,41.2) v1(21.17,61.5) v1(21.17,36.6) v1(21.22,88.15) v1(21.27,60.85) v1(21.32,34.85) v1(21.55,45.1) v1(21.52,39.97) v1(21.62,66.53) v1(21.6,63.35) v1(21.62,45.82) v1(21.6,37.68) v1(21.8,68.82) v1(21.78,56.23) v1(21.72,44.43) v1(21.88,69.68) v1(21.82,60.85) v1(21.9,46.51) v1(21.95,42.18) v1(21.92,36.57) v1(21.95,26.9) v1(22.1,85.75) v1(22.27,43.65) v1(22.32,44.65) v1(22.47,49.88) v1(22.47,38.9) v1(22.62,42.85) v1(22.66,40.97) v1(22.67,36.6) v1(22.66,28.97) v1(22.71,32.44) v1(22.88,42.2) v1(22.9,41.57) v1(22.97,44.07) v1(22.96,43.37) v1(23.05,40.53) v1(23.19,26.8) v1(23.23,46.91) v1(23.4,51.2) v1(23.4,45.95) v1(23.42,50.53) v1(23.45,40.05) v1(23.45,36.6) v1(23.55,46.47) v1(23.55,37.72) v1(23.67,49.22) v1(23.7,38.72) v1(23.88,39.68) v1(24.15,88.02) v1(24.2,36.57) v1(24.27,39.28) v1(24.32,59.35) v1(24.52,66.1) v1(24.5,60.88) v1(24.67,63.78) v1(24.62,42.78) v1(24.65,42.1) v1(24.6,38.85) v1(24.66,26.97) v1(24.8,85.75) v1(24.7,69.62) v1(24.72,44.95) v1(24.73,41.48) v1(24.71,30.74) v1(24.88,71.95) v1(24.92,79.5) v1(24.94,44.51) v1(24.92,37.32) v1(24.97,36.57) v1(25.05,38.45) v1(25.15,67.1) v1(25.15,60.88) v1(25.17,42.35) v1(25.17,41.06) v1(25.3,82.23) v1(25.25,45.1) v1(25.25,41.78) v1(25.4,38) v1(25.42,48.25) v1(25.46,44.5) v1(25.57,64.68) v1(25.62,40.62) v1(25.8,59.18) v1(25.75,41.93) v1(25.7,36.6) v1(25.73,26.8) v1(25.82,60.88) v1(25.85,56.87) v1(25.9,45.78) v1(25.85,44.12) v1(25.9,41.3) v1(25.82,37.6) v1(26.05,83.3) v1(26.02,40.2) v1(26.15,43.55) v1(26.22,73.28) v1(26.25,40.85) v1(26.27,37.28) v1(26.27,36.6) v1(26.42,39.78) v1(26.52,65.95) v1(26.59,46.01) v1(26.65,43.19) v1(26.66,28.97) v1(26.7,88.05) v1(26.72,69.6) v1(26.75,68.82) v1(26.75,67.12) v1(26.75,63.72) v1(26.72,61.7) v1(26.75,46.57) v1(26.78,43.88) v1(26.75,36.9) v1(26.71,32.44) v1(26.82,71.4) v1(26.9,26.95) v1(26.92,42.62) v1(26.95,41) v1(26.95,40.38) v1(26.97,39.78) v1(26.97,39.22) v1(27,81.43) v1(27.17,36.6) v1(27.32,61.68) v1(27.42,85.68) v1(27.42,38.8) v1(27.45,29.88) v1(27.55,34.88) v1(27.65,70.4) v1(27.6,64.7) v1(27.8,73.62) v1(27.8,57.53) v1(27.75,39.22) v1(27.8,36.65) v1(27.95,61.68) v1(27.95,38.47) v1(28.07,26.82) v1(28.15,31.75) v1(28.15,31.1) v1(28.1,30.5) v1(28.15,29.32) v1(28.15,28.7) v1(28.12,28.03) v1(28.2,27.38) v1(28.22,54.12) v1(28.22,53.12) v1(28.22,52.12) v1(28.22,51.12) v1(28.24,32.46) v1(28.45,57.47) v1(28.42,36.66) v1(28.55,71.5) v1(28.58,43.35) v1(28.56,40.75) v1(28.65,73.3) v1(28.61,42.62) v1(28.7,63.6) v1(28.8,60.93) v1(28.77,46.88) v1(28.8,46.22) v1(28.8,45.6) v1(28.77,44.55) v1(28.77,43.97) v1(28.8,32.72) v1(28.82,85.73) v1(28.89,41.28) v1(29.07,39.5) v1(29.05,36.65) v1(29.16,42.61) v1(29.25,88.05) v1(29.22,57.55) v1(29.22,54.12) v1(29.25,53.12) v1(29.22,52.12) v1(29.22,51.12) v1(29.22,43.33) v1(29.25,40.85) v1(29.4,72.38) v1(29.38,46.25) v1(29.52,32.72) v1(29.66,42.91) v1(29.65,39.5) v1(29.75,60.93) v1(29.72,36.65) v1(29.85,82.73) v1(29.88,80) v1(29.84,43.68) v1(29.82,41.31) v1(29.97,85.65) v1(30.07,30.28) v1(30.02,29.7) v1(30.07,28.22) v1(30.17,40.68) v1(30.17,39.61) v1(30.15,32.7) v1(30.1,26.88) v1(30.22,54.12) v1(30.27,53.12) v1(30.25,52.12) v1(30.22,51.12) v1(30.22,27.6) v1(30.31,43.16) v1(30.38,39.15) v1(30.32,36.6) v1(30.43,41.3) v1(30.44,30.75) v1(30.69,40.12) v1(30.66,28.97) v1(30.72,38.43) v1(30.72,37.9) v1(30.74,37.09) v1(30.77,32.65) v1(31.07,41.38) v1(31.07,40.7) v1(31,36.62) v1(31.07,30.72) v1(31.2,26.93) v1(31.22,54.12) v1(31.22,53.12) v1(31.22,52.12) v1(31.22,51.12) v1(31.4,32.75) v1(31.77,85.68) v1(31.73,44.02) v1(31.85,88.12) v1(31.85,84.88) v1(32.02,33.78) v1(32.02,32.82) v1(32.02,30.72) v1(32.05,30.12) v1(32.07,29.47) v1(32.09,26.8) v1(32.1,79.1) v1(32.2,41.22) v1(32.17,40.68) v1(32.17,40.18) v1(32.15,39.7) v1(32.35,71.2) v1(32.39,43.6) v1(32.52,41.72) v1(32.61,46.39) v1(32.65,45.93) v1(32.82,80.85) v1(32.85,29.45) v1(32.97,40.62) v1(33.11,41.52) v1(33.2,39.7) v1(33.35,42.3) v1(33.38,26.85) v1(33.52,41.2) v1(33.65,29.45) v1(33.62,28.2) v1(33.72,45.68) v1(33.76,41.97) v1(33.74,39.63) v1(33.79,37.79) v1(33.85,46.28) v1(33.85,44.5) v1(33.82,40.15) v1(33.9,32.32) v1(33.9,31.7) v1(33.97,73.78) v1(33.95,40.7) v1(33.96,37.04) v1(33.97,36.46) v1(33.97,35.9) v1(33.95,34.18) v1(34.02,32.97) v1(34.15,33.5) v1(34.3,88.15) v1(34.27,45.57) v1(34.27,44.07) v1(34.25,31.25) v1(34.35,84.98) v1(34.35,37.78) v1(34.42,29.45) v1(34.6,27.78) v1(34.67,46.3) v1(34.69,44.66) v1(34.66,28.97) v1(34.63,26.8) v1(34.7,86.1) v1(34.78,45.18) v1(34.75,43.68) v1(34.89,37.94) v1(34.91,37.29) v1(35.07,77.57) v1(35.02,31.25) v1(35.11,44.22) v1(35.2,43.25) v1(35.1,34.3) v1(35.15,29.47) v1(35.3,45.97) v1(35.24,38.26) v1(35.3,36.6) v1(35.35,80.38) v1(35.47,78.9) v1(35.41,44.84) v1(35.67,43.5) v1(35.67,42.88) v1(35.6,42.28) v1(35.65,41.63) v1(35.67,40.35) v1(35.67,39.75) v1(35.67,39.18) v1(35.62,38.6) v1(35.79,45.48) v1(35.75,37.03) v1(35.77,31.28) v1(35.8,29.45) v1(35.84,55.55) v1(35.82,54.8) v1(35.81,49.55) v1(35.88,43.98) v1(35.81,40.94) v1(35.95,34.53) v1(36.05,28.88) v1(36.1,31.82) v1(36.77,47.43) v1(36.85,67.53) v1(36.97,88.18) v1(36.97,86.48) v1(36.94,36.62) v1(37.02,34.28) v1(37.12,43.62) v1(37.15,43.07) v1(37.27,73.18) v1(37.3,48.75) v1(37.3,39.15) v1(37.25,32.93) v1(37.25,26.9) v1(37.35,47.18) v1(37.38,37.82) v1(37.42,40.68) v1(37.47,36.68) v1(37.52,41.85) v1(37.52,27.57) v1(37.65,46.72) v1(37.62,42.65) v1(37.7,66.97) v1(38.05,80.73) v1(38.07,57.15) v1(38.12,46.78) v1(38.12,36.62) v1(38.25,42.65) v1(38.3,38.85) v1(38.35,34.6) v1(38.57,26.88) v1(38.66,40.97) v1(38.66,36.97) v1(38.72,46.72) v1(38.7,33.38) v1(38.9,77.78) v1(38.95,60.7) v1(38.95,56.38) v1(38.95,36.45) v1(39.17,46.53) v1(39.15,45.18) v1(39.17,44.5) v1(39.12,37.9) v1(39.27,59.85) v1(39.27,55.4) v1(39.32,66.57) v1(39.38,43) v1(39.47,86.45) v1(39.45,41.97) v1(39.42,40.15) v1(39.47,39.15) v1(39.52,88.18) v1(39.55,36.6) v1(39.6,26.93) v1(39.72,46.35) v1(39.75,27.57) v1(39.85,33.93) v1(39.97,43.2) v1(40.07,36.57) v1(40.15,55.88) v1(40.17,37.8) v1(40.15,33.15) v1(40.3,45.18) v1(40.25,44.5) v1(40.35,48.4) v1(40.5,46.85) v1(40.52,41.22) v1(40.66,38.97) v1(40.67,36.6) v1(40.85,40.15) v1(40.95,42.95) v1(41.05,45.38) v1(41.1,71.3) v1(41.15,67.03) v1(41.17,57.25) v1(41.15,34.6) v1(41.22,55.32) v1(41.27,37.5) v1(41.27,36.57) v1(41.32,64.57) v1(41.42,28.88) v1(41.5,31.8) v1(41.65,80.88) v1(41.62,44.1) v1(41.62,42.12) v1(41.75,72.05) v1(41.7,40.97) v1(41.85,36.6) v1(41.88,30.22) v1(41.97,78.18) v1(42.07,45.47) v1(42.1,86.8) v1(42.17,85.05) v1(42.12,40.03) v1(42.25,56.85) v1(42.27,56.05) v1(42.27,54.4) v1(42.27,50.78) v1(42.22,44.88) v1(42.3,44.12) v1(42.3,43.4) v1(42.3,42.8) v1(42.3,42.18) v1(42.3,41.57) v1(42.22,38.95) v1(42.22,38.32) v1(42.25,37.68) v1(42.25,37.1) v1(42.32,55.35) v1(42.32,51.38) v1(42.52,88.15) v1(42.55,40.45) v1(42.52,39.5) v1(42.57,34.4) v1(42.9,57.2) v1(42.9,33.18) v1(42.88,27.9) v1(42.97,26.9) v1(43.02,62.85) v1(43.4,86.8) v1(43.35,30.6) v1(43.42,82.4) v1(43.52,29.28) v1(43.62,65.7) v1(43.65,58.72) v1(43.67,57.97) v1(43.67,57.25) v1(43.62,32.2) v1(43.85,52.88) v1(44.05,68.68) v1(44.12,28.18) v1(44.1,26.88) v1(44.32,52.32) v1(44.35,39.28) v1(44.45,33.5) v1(44.51,87.81) v1(44.55,67.57) v1(44.5,41.93) v1(44.6,83.5) v1(44.7,61.18) v1(44.72,49.85) v1(45,30.18) v1(45.12,86.8) v1(45.27,70.75) v1(45.4,63.65) v1(45.32,32.55) v1(45.4,26.95) v1(45.57,56.68) v1(45.5,50.68) v1(45.72,53.35) v1(46.07,83.48) v1(46.02,68.62) v1(46.35,66.8) v1(46.52,70.78) v1(46.55,26.97) v1(46.66,28.97) v1(46.7,32) v1(47.05,87.81) v1(47,86.82) v1(47.2,67.25) v1(47.12,65.38) v1(47.12,58.85) v1(47.35,70.8) v1(47.33,26.8) v1(47.47,56.32) v1(47.52,53.75) v1(47.7,61.5) v1(47.82,69.55) v1(47.92,51.05) v1(48.2,65.32) v1(48.2,48) v1(48.27,85.52) v1(48.25,66.5) v1(48.57,32.75) v1(48.66,26.97) v1(48.8,30.55) v1(48.85,70.9) v1(49.25,56.97) v1(49.42,84.32) v1(49.59,87.81) v1(49.8,85.95) v1(49.88,31.72) v1(49.87,26.8) v1(50,83.43) v1(50.2,62.18) v1(50.32,37.88) v1(50.66,32.97) v1(50.66,28.97) v1(50.7,70.4) v1(50.82,65.45) v1(51.05,26.85) v1(51.1,84.4) v1(51.25,83.45) v1(51.33,87.21) v1(51.38,71.72) v1(51.45,42.25) v1(52.13,87.81) v1(52.15,85.6) v1(52.1,70.65) v1(52.22,77.8) v1(52.41,26.8) v1(52.8,64.62) v1(52.77,30.6) v1(53,78.85) v1(53.02,42.93) v1(53.07,39.25) v1(53.22,75.93) v1(53.57,84.27) v1(53.5,81.27) v1(53.7,26.88) v1(53.95,35.38) v1(54.07,31.55) v1(54.66,32.97) v1(54.66,28.97) v1(54.94,74.89) v1(54.95,26.8) v1(55.17,35.82) v1(55.3,42.88) v1(55.25,38.7) v1(55.32,79.82) v1(55.5,82.57) v1(55.85,52.62) v1(55.9,50.25) v1(55.88,26.85) v1(55.97,40.07) v1(55.97,37.8) v1(56.1,66.85) v1(56.1,64.31) v1(56.1,62.47) v1(56.07,57.82) v1(56.02,55.47) v1(56.05,45.38) v1(56.07,42.78) v1(56.15,60.2) v1(56.18,47.57) v1(56.66,70.97) v1(56.66,34.97) v1(56.66,30.97) v1(56.66,26.97) v1(56.93,79.22) v1(57.35,83.2) v1(57.32,68.25) v1(57.42,69.86) v1(57.49,26.8) v1(57.57,66.18) v1(57.65,63.85) v1(57.65,27.97) v1(57.74,81.28) v1(57.75,62.35) v1(57.75,59.81) v1(57.75,57.27) v1(57.75,54.73) v1(57.75,52.19) v1(57.75,49.65) v1(57.75,47.11) v1(57.75,44.57) v1(57.75,42.03) v1(57.75,39.49) v1(57.75,36.95) v1(57.75,34.41) v1(57.75,31.87) v1(57.75,29.33)
VDDR: length 38.6
  TOP w0.15: v1(25.1,50.65) 25.07,50.65 24.92,50.5 C7.1 ; 25.25,48.99 v1(25.25,49.15)
  TOP w0.25: 25.22,49.15 25.67,49.6 U1.64 ; 25.22,49.15 C8.1 ; 25.22,49.15 v1(25.25,49.15) ; v1(25.1,50.65) 25.18,50.72 25.32,50.72 25.34,50.75 25.4,50.75 25.45,50.8 U1.61
  TOP w0.5: v1(22.62,47.2) 22.62,47.64 23.5,48.51 24.78,48.51 25.25,48.99 ; 31.17,42.6 v1(30.76,42.18) ; L1.1 27.37,60.4 27.85,59.93 C1.1
  L3 w0.3: v1(25.1,50.65) 24.42,50.65
  L3 w0.5: v1(30.76,42.18) 30.6,42.03 26.67,42.03 24.83,43.86 23.98,43.86 22.62,45.22 v1(22.62,47.2) ; 29.4,58.47 22.8,58.47 22.07,57.74 22.07,56.96 24.42,54.6 24.42,49.98 v1(25.25,49.15)
  vias: v1(29.42,59.43) v1(29.55,59) v1(29.55,58.47)
VDDS: length 40.5
  TOP w0.15: U1.30 v1(34.27,54.8) C5.1 ; v1(24.52,55.6) R1.2 ; C6.1 v1(25.12,51.2)
  TOP w0.25: U1.48 26.75,57.03 C3.1 26.38,57.6 26.03,57.95 25.52,57.95 C2.1 24.85,58.43 v1(24.2,57.78) ; U1.17 34.72,49.6 34.75,49.57 C4.1 34.75,49.9 v1(34.95,50.1) ; U1.60 v1(25.12,51.2)
  TOP w0.3: FL1.1 23,57.9 23.15,57.75
  TOP w0.4: 29.38,44.28 29.35,44.31 v1(29.35,44.98)
  L3 w0.3: 25.12,51.6 v1(25.12,51.2)
  L3 w0.5: v1(34.27,54.8) 34.15,54.68 32.67,54.68 ; 25.12,55.03 25.62,55.03 26.8,56.2 28.82,56.2 30.34,54.69 31.46,54.69 31.47,54.68 32.67,54.68 ; 25.12,55.03 24.55,55.6 v1(24.52,55.6) 23.67,56.45 23.67,56.9 ; 25.12,55.03 25.12,51.6 ; v1(29.35,44.98) 31.72,47.36 31.72,49.35 32.72,50.35 ; 32.72,50.35 32.67,50.4 32.67,54.68 ; 32.72,50.35 32.88,50.5 34.52,50.5 34.92,50.1 v1(34.95,50.1)
  vias: v1(22.67,57.49) v1(23.15,57.7) v1(23.2,57.12) v1(23.66,57.58)
BP_RESET: length 18.9
  TOP w0.15: R9.1 38.27,68.31 38.42,68.16 38.42,68.12 ; 38.42,68.12 38.6,68.31 R8.1 ; 38.42,68.12 v1(38.42,67.68)
  L3 w0.15: J2.11 49.14,55.76 38.42,66.48 v1(38.42,67.68)
DIO3: length 30.8
  TOP w0.15: P4.1 10.15,40.53 R16.1 ; U1.12 v1(31.15,49.7)
  L3 w0.15: v1(31.15,49.7) 30.42,50.43 29.2,50.43 28.72,49.95 28.7,49.95 26.29,47.54 26.27,47.54 26.17,47.45 24.58,47.45 23.5,48.53 22.88,48.53 19.55,45.2 13.17,45.2 11.82,43.85 10.65,43.85 10.14,43.34 P4.1
DIO3_RF_PA: length 32.9
  TOP w0.15: R16.2 10.16,43 v1(10.65,43) ; v1(32.02,38.15) 31.82,38.35 U2.3
  L3 w0.15: v1(10.65,43) 10.65,42.48 11.32,41.8 11.32,34.53 11.52,34.32 29.25,34.32 31.77,36.85 31.77,37.9 v1(32.02,38.15)
DIO4_SCL: length 64
  TOP w0.15: v1(36.97,46.75) 36.75,46.75 36.61,46.61 36.13,46.61 35.42,47.32 33.12,47.32 33.04,47.41 32.39,47.41 31.55,48.26 U1.13 ; J1.17 5.17,46.97 R3.1
  L3 w0.15: J1.17 6.33,47.09 5.28,46.03 5.28,45.16 5.9,44.55 6.03,44.55 8.75,41.83 8.75,34.57 9.6,33.72 29.5,33.72 30.8,35.03 34.77,35.03 36.65,36.9 36.65,38.6 36.67,38.62 36.67,46.45 v1(36.97,46.75)
DIO5_SDA: length 58.8
  TOP w0.15: v1(36.31,47.03) 36.19,47.03 35.6,47.62 33.25,47.62 33.16,47.71 32.52,47.71 31.95,48.28 U1.14 ; J1.19 5.11,44.38 R2.1
  L3 w0.15: J1.19 6.8,45.6 8.96,43.44 8.96,43.14 8.97,43.13 8.97,42.03 9.05,41.95 9.05,34.7 9.72,34.03 29.38,34.03 30.68,35.33 34.65,35.33 36.35,37.03 36.35,44.15 36.31,44.18 v1(36.31,47.03)
DIO6_RLED: length 39.9
  TOP w0.15: v1(39.17,49.32) 39.05,49.32 37.65,47.93 33.38,47.93 33.29,48.01 32.64,48.01 32.35,48.31 U1.15
  L3 w0.15: P1.2 18.27,67.81 23.38,62.7 29.57,62.7 32.2,60.07 32.2,60.07 32.97,59.3 32.97,59.3 35.3,56.97 36.23,56.97 37.92,55.28 37.92,53.17 37.57,52.82 37.57,50.73 38.98,49.32 v1(39.17,49.32)
DIO7_GLED: length 41.3
  TOP w0.15: U1.16 32.75,48.56 32.98,48.32 33.4,48.32 33.5,48.22 34.44,48.22 34.46,48.25 37.47,48.25 v1(39.15,49.93)
  L3 w0.15: v1(39.15,49.93) 38.8,49.93 37.88,50.85 37.88,52.7 38.22,53.05 38.22,55.41 36.36,57.28 35.42,57.28 33.27,59.42 33.27,59.43 32.33,60.38 32.32,60.38 29.65,63.05 23.55,63.05 19.76,66.84 19.76,68.97 18.27,70.46 P1.4
DIO8_MISO: length 32.9
  TOP w0.15: v1(42.3,49.4) 42.25,49.4 42.13,49.53 42.12,49.53 42,49.65 40.8,49.65 40.07,50.38 35.28,50.38 35.13,50.53 34.67,50.53 34.15,50 U1.18
  L3 w0.15: J2.14 53.9,51.39 53.9,45 52.5,43.6 48.1,43.6 v1(42.3,49.4)
DIO9_MOSI: length 37.4
  TOP w0.15: v1(42.3,49.95) 40.92,49.95 40.2,50.68 35.4,50.68 35.25,50.83 34.55,50.83 34.22,50.5 34.22,50.5 34.12,50.4 U1.19
  L3 w0.15: v1(42.3,49.95) 42.27,49.93 42.1,49.93 41.88,49.7 41.88,49.22 47.8,43.3 52.62,43.3 54.2,44.88 54.2,51.52 53.35,52.37 53.35,54.45 52.07,55.73 J2.12
DIO10_SCLK: length 87.2
  TOP w0.15: U1.20 34.1,50.8 34.42,51.13 36.25,51.13 v1(36.25,51.12)
  L3 w0.15: v1(36.25,51.12) 36.25,50.35 38.6,48 40.97,48 47.35,41.62 48.75,41.62 49.47,40.9 49.47,39.82 48.98,39.33 45.3,39.33 44.3,38.32 44.3,37.4 42.96,36.06 36.24,36.06 34.9,34.72 30.93,34.72 29.63,33.43 9.47,33.43 8.45,34.45 8.45,41.62 5.82,44.25 5.77,44.25 4.98,45.04 4.98,51.87 J1.13
DIO11: length 43
  TOP w0.15: U1.21 34.07,51.2 34.34,51.47 35.37,51.47 35.47,51.57 38.05,51.57 v1(38.47,51.15)
  L3 w0.15: J2.6 50.97,62.28 50.97,59.93 51.38,59.53 51.38,59.09 50.65,58.36 50.65,47.3 50.38,47.03 49.05,47.03 48.45,46.43 47.52,46.43 44.22,49.72 44.22,51.78 40.7,55.3 39.88,55.3 39.2,54.62 39.2,52.92 39.31,52.81 39.31,52.46 39.12,52.27 39.12,51.8 v1(38.47,51.15)
DIO14_BTN2: length 51.9
  TOP w0.15: v1(54.95,60.84) J2.8 ; R13.2 55.72,69.86 v1(54.95,69.09) ; U1.28 36.32,54 36.47,54.15 39.12,54.15 39.35,53.93 v1(39.62,53.93)
  L3 w0.15: v1(54.95,60.84) v1(54.95,69.09) ; J2.8 53.2,59.71 53.2,57.8 52.4,57 51.32,57 51.02,56.7 51.02,47.71 51.02,47.7 51.02,47.18 50.5,46.65 49.1,46.65 48.57,46.12 47.4,46.12 43.92,49.6 43.92,51.65 40.62,54.95 39.97,54.95 39.62,54.6 v1(39.62,53.93)
DIO15_BTN1: length 86.7
  TOP w0.15: v1(40.15,54.5) 36.28,54.5 36.1,54.32 34.15,54.32 34.1,54.38 34.07,54.38 34.05,54.4 U1.29 ; R12.2 6.48,73.22 7.85,73.22 8.59,72.49 v1(9.49,72.49)
  L3 w0.15: J2.20 50.97,44.5 48.6,44.5 43.62,49.47 43.62,51.53 41.2,53.95 41.15,53.95 40.6,54.5 v1(40.15,54.5) 40.15,53.85 39.61,53.31 39.61,52.33 39.49,52.21 39.49,51.11 39.6,51 39.6,49.15 39.35,48.9 38.98,48.9 37.27,50.6 37.27,52.67 36.55,53.4 36.55,55.38 35.86,56.07 34.92,56.07 32.07,58.92 32.07,58.93 31.83,59.18 31.82,59.18 30.51,60.49 25.29,60.49 24.88,60.08 22.88,60.08 20.97,58.17 20.97,57.43 20.62,57.08 20.32,57.08 19.78,56.54 13.06,56.54 12.42,57.18 12.42,69.55 v1(9.49,72.49)
DIO16_TDO: length 67.5
  TOP w0.15: v1(33.95,71) 32.86,69.91 R6.2 ; CR2.5 v1(49.77,82.55) ; v1(36.92,60.4) 36.92,59.95 35.42,58.44 33.92,58.44 32.35,56.88 U1.34 ; v1(46.85,78.65) 46.85,78.53 46.52,78.19 P6.6 46.52,75.36 45.86,74.7 43.5,74.7 41.85,73.05 v1(41.85,72.97)
  L3 w0.15: v1(36.92,60.4) 36.92,60.73 36.1,61.55 33.3,61.55 28.8,66.05 28.8,69.03 30.57,70.8 33.75,70.8 v1(33.95,71) 33.95,71.1 34.4,71.55 34.4,71.78 35.6,72.97 36.45,72.97 36.95,72.47 39.62,72.47 40.38,73.22 40.88,73.22 41.05,73.4 41.42,73.4 v1(41.85,72.97) ; J4.4 39.27,85.88 46.6,85.88 48.6,83.88 48.6,83.5 49.55,82.55 v1(49.77,82.55) 49.92,82.55 50.32,82.15 50.32,81.13 48.5,79.3 47.25,79.3 46.85,78.9 v1(46.85,78.65)
DIO17_TDI: length 78.5
  TOP w0.15: U1.35 31.95,57.01 33.69,58.74 35.29,58.74 36.32,59.78 36.32,60.72 v1(36.15,60.9) ; R7.2 31.37,69.91 32.07,70.61 32.73,70.61 v1(33.47,71.35) ; v1(52.7,82.55) CR2.3 ; v1(47.88,78.65) 47.88,78.03 47.79,77.94 P6.8 v1(47.79,74.82)
  L3 w0.15: v1(47.88,78.65) 48.35,78.65 50.82,81.12 51.95,81.12 52.1,81.27 52.1,81.95 v1(52.7,82.55) 52.65,82.6 50.33,82.6 49.95,82.98 49.92,82.98 49.86,83.04 49.84,83.04 49.61,83.26 49.61,83.29 46.67,86.23 41.48,86.23 40.69,87.01 J4.2 ; v1(36.15,60.9) 34.95,60.9 34.6,61.25 33.18,61.25 28.5,65.93 28.5,69.15 30.94,71.59 32.51,71.59 32.74,71.35 v1(33.47,71.35) 33.55,71.35 35.47,73.28 36.58,73.28 37.08,72.78 39.5,72.78 40.25,73.53 40.75,73.53 40.97,73.75 41.68,73.75 42.27,73.15 42.27,70.07 42.97,69.38 46.52,69.38 47.79,70.64 v1(47.79,74.82)
DIO19: length 54.7
  TOP w0.15: v1(34.65,59.93) 34.6,59.88 33.7,59.88 33.35,59.53 33.35,59.28 32.05,57.98 32.05,57.97 31.63,57.55 31.62,57.55 31.15,57.08 U1.37
  L3 w0.15: v1(34.65,59.93) 34.9,60.18 36.02,60.18 36.4,59.8 36.44,59.8 36.94,59.3 38.05,59.3 38.77,58.58 39.12,58.58 39.12,58.57 42.08,58.57 42.32,58.82 42.32,59.18 42.08,59.43 42.08,59.43 38.15,63.35 34.05,63.35 30.6,66.8 30.6,68.28 31.32,69 42.58,69 46.83,64.75 50.9,64.75 J2.4
DIO20: length 52.8
  TOP w0.15: U1.38 30.75,57.1 31.49,57.85 31.5,57.85 31.75,58.1 31.75,58.1 33,59.35 33,59.6 33.75,60.35 34.92,60.35 v1(35.55,59.72)
  L3 w0.15: J2.5 47.77,63.38 42.45,68.7 31.45,68.7 30.9,68.15 30.9,66.93 34.18,63.65 38.28,63.65 42.2,59.72 42.62,59.3 42.62,58.7 42.2,58.28 38.55,58.28 37.88,58.95 36.86,58.95 36.31,59.5 36.27,59.5 36.07,59.7 35.57,59.7 v1(35.55,59.72)
DIO21: length 40.1
  TOP w0.15: U1.39 30.35,57.15 31.32,58.12 v1(31.32,58.28)
  L3 w0.15: v1(31.32,58.28) 31.32,58.47 29.95,59.85 25.8,59.85 24.91,58.96 22.61,58.96 21.57,57.92 21.57,57 21.34,56.76 21.34,56.12 21.69,55.78 22.58,55.78 23.9,54.45 23.9,52.25 22.98,51.32 15.67,51.32 13.83,49.49 7.53,49.49 J1.15
DIO22: length 40.9
  TOP w0.15: U1.40 29.95,57.18 30.9,58.12 30.9,58.6 31.05,58.75 v1(31.65,58.75)
  L3 w0.15: v1(31.65,58.75) 30.21,60.19 25.41,60.19 25,59.78 23,59.78 21.27,58.05 21.27,57.12 21.04,56.89 21.04,56 21.56,55.47 22.45,55.47 23.35,54.58 23.35,53.45 22.78,52.88 21.75,52.88 19.9,54.72 19.55,54.72 19.55,54.72 13.37,54.72 13.36,54.74 12.31,54.74 10.35,56.7 10.35,56.75 10.2,56.9 8.25,56.9 6.85,58.3 J1.9
DIO23_ANALOG: length 27.6
  TOP w0.15: v1(21.66,54.62) 22.28,55.25 23.5,55.25 23.7,55.05 24.67,55.05 24.82,55.2 U1.50
  L3 w0.15: v1(21.66,54.62) 21.4,54.88 21.25,54.88 20.48,55.64 12.69,55.64 11.25,57.08 11.25,58.12 10.45,58.92 10.45,60.97 9.3,62.12 8.25,62.12 7.82,62.55 7.82,62.94 7.82,62.94 7.82,63.81 7.82,63.82 7.82,64.43 J1.3
DIO24_ANALOG: length 21.5
  TOP w0.15: U1.51 25.82,54.88 24.92,54.88 24.8,54.75 23.58,54.75 23.38,54.95 22.58,54.95 22.5,54.88 22.42,54.88 22.17,54.63 22.17,54.54 21.06,53.43 20.75,53.43 20.7,53.38 v1(19.7,53.38)
  L3 w0.15: J1.11 7.67,54.43 11.78,54.43 12.06,54.14 13.11,54.14 13.12,54.12 19.07,54.12 19.7,53.5 v1(19.7,53.38)
DIO25_ANALOG: length 23.1
  TOP w0.15: v1(22.6,54.45) 24.75,54.45 24.8,54.4 U1.52
  L3 w0.15: v1(22.6,54.45) 22.6,54.9 22.33,55.18 21.44,55.18 20.67,55.94 12.81,55.94 11.55,57.2 11.55,58.25 10.75,59.05 10.75,61.35 8.87,63.23 J1.6
DIO26_ANALOG: length 21.4
  TOP w0.15: U1.53 24.72,54 24.57,54.15 23.4,54.15 23.35,54.1 22.85,54.1 22.78,54.03 22.65,54.03 22.22,53.6 v1(22.15,53.6)
  L3 w0.15: v1(22.15,53.6) 22.07,53.6 21.48,54.19 21.48,54.19 20.35,55.32 13.62,55.32 13.61,55.34 12.56,55.34 10.95,56.95 10.95,58 10.1,58.85 10.1,59.61 J1.8
DIO27_ANALOG: length 20
  TOP w0.15: v1(22.92,53.62) 22.97,53.68 23.88,53.68 23.95,53.6 U1.54
  L3 w0.15: J1.10 10.22,58.3 10.65,57.87 10.65,56.83 12.44,55.04 13.48,55.04 13.5,55.03 20.12,55.03 21.97,53.18 22.33,53.18 22.78,53.62 v1(22.92,53.62)
DIO28_ANALOG: length 18.3
  TOP w0.15: U1.55 23.05,53.2 22.85,53 v1(20.92,53)
  L3 w0.15: v1(20.92,53) 20.85,53 19.43,54.43 13.25,54.43 13.23,54.44 12.19,54.44 10.87,55.76 J1.12
DIO29_ANALOG: length 18.1
  TOP w0.15: U1.56 24.02,52.8 24,52.82 23.1,52.82 22.85,52.58 v1(22.85,52.45)
  L3 w0.15: v1(22.85,52.45) 22.8,52.4 20.07,52.4 18.65,53.82 9.48,53.82 J1.14
DIO30_ANALOG: length 19.1
  TOP w0.15: U1.57 v1(23.45,52.4)
  L3 w0.15: J1.16 8.87,50.85 11.52,53.5 18.52,53.5 20.05,51.97 22.98,51.97 23.4,52.4 v1(23.45,52.4)
DIO34: length 23.7
  TOP w0.15: v1(34.24,48.66) 34.3,48.72 R17.2 ; U1.10 30.35,49.19 30.19,49.35 30.19,49.44 29.79,49.84 v1(29.79,49.93)
  L3 w0.15: v1(34.24,48.66) 35.08,47.82 37.75,47.82 38.2,47.38 40.75,47.38 45.72,42.4 P5.1
  BOTTOM w0.15: v1(34.24,48.66) 34.24,48.61 33.8,48.18 30.83,48.18 29.79,49.21 v1(29.79,49.93)
DIO34_RF_2G4: length 20.6
  TOP w0.15: v1(28.83,38.05) 28.95,37.93 29.51,37.93 29.53,37.95 U2.7 ; v1(35.8,48.7) 35.77,48.72 R17.1
  L3 w0.15: v1(28.83,38.05) 29,37.88 30.2,37.88 30.56,37.51 30.88,37.51 31.11,37.74 31.11,39.26 31.77,39.93 31.77,41.53 33.28,43.03 33.28,45.2 33.34,45.26 33.34,46.86 32.6,47.6 32.6,48.95 33.2,49.55 34.38,49.55 34.54,49.39 34.54,49.39 35.1,48.82 35.12,48.82 35.25,48.7 v1(35.8,48.7)
